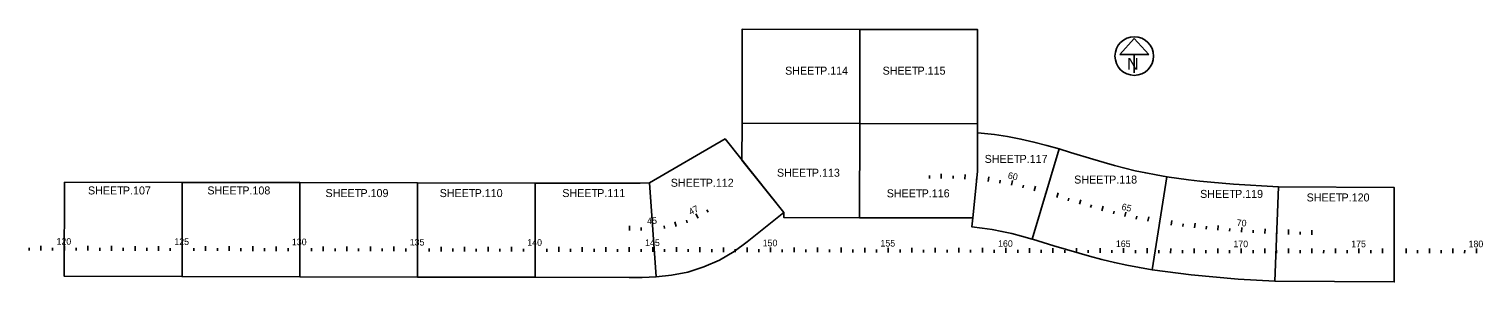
# Model space of a CAD drawing. Extents: x 129683 to 135859, y 574888 to 575962.
import ezdxf

# ---------------------------------------------------------------- set-up
doc = ezdxf.new("R2010")
doc.units = 0
for name, color, linetype in [('GE_P_Alignment_100_Stations', 7, 'Continuous'), ('SH_Masking', 7, 'Continuous'), ('SH_Named_Boundary', 7, 'Continuous'), ('SH_Text', 7, 'Continuous')]:
    doc.layers.add(name, color=color, linetype=linetype)

msp = doc.modelspace()

# ---------------------------------------------------------------- linework, layer by layer
at = {"layer": 'GE_P_Alignment_100_Stations'}
for p, q in [((133558.3, 575328), (133558.3, 575348)), ((133658.2, 575325.2), (133659.4, 575345.2)), ((133508.3, 575328.1), (133508.3, 575340.1)), ((133608.2, 575327.4), (133608.6, 575339.4)), ((133708, 575321.2), (133709.2, 575333.2)), ((133757.7, 575315.5), (133760.3, 575335.3)), ((133807.1, 575308.1), (133809.1, 575319.9)), ((133856.3, 575298.9), (133860.3, 575318.5)), ((133905.1, 575288), (133907.9, 575299.7)), ((133953.5, 575275.4), (133958.9, 575294.7)), ((134001.5, 575261.3), (134004.9, 575272.8)), ((134049.3, 575247), (134055.1, 575266.1)), ((134097.2, 575232.6), (134100.7, 575244.1)), ((134145.1, 575218.3), (134150.9, 575237.4)), ((132525.3, 575159.5), (132516.2, 575177.3)), ((132568.5, 575184.6), (132561.9, 575194.6)), ((134193, 575203.9), (134196.4, 575215.4)), ((134241.1, 575190.2), (134246.4, 575209.4)), ((134289.5, 575177.5), (134292.4, 575189.1)), ((134338.1, 575165.8), (134342.5, 575185.3)), ((134387, 575155.3), (134389.4, 575167)), ((134436, 575145.8), (134439.6, 575165.4)), ((132233.2, 575107.1), (132233.2, 575127.1)), ((132283.2, 575107.4), (132282.9, 575119.4)), ((132333.1, 575109.5), (132331.7, 575129.4)), ((132382.8, 575114.7), (132381.1, 575126.6)), ((132431.9, 575124.4), (132426.9, 575143.7)), ((132479.5, 575139.3), (132475.3, 575150.6)), ((134485.3, 575137.3), (134487.2, 575149.2)), ((134534.8, 575130), (134537.5, 575149.8)), ((134584.4, 575123.6), (134585.8, 575135.5)), ((134634, 575117.8), (134636.3, 575137.7)), ((134683.8, 575112.5), (134685, 575124.5)), ((134733.5, 575107.8), (134735.3, 575127.7)), ((134783.4, 575103.5), (134784.3, 575115.5)), ((134833.2, 575099.9), (134834.6, 575119.8)), ((134883.1, 575096.7), (134883.8, 575108.7)), ((134933, 575094.1), (134934, 575114)), ((134983, 575091.9), (134983.4, 575103.9)), ((135033, 575090.4), (135033.5, 575110.4)), ((135083, 575089.3), (135083.2, 575101.3)), ((135133, 575088.8), (135133.1, 575108.8)), ((129733, 575021.7), (129733, 575041.7)), ((129833, 575021.4), (129833, 575041.4)), ((129933, 575021.2), (129933, 575041.2)), ((130033, 575021), (130033, 575041)), ((130133, 575020.8), (130133, 575040.8)), ((130233, 575020.5), (130233, 575040.5)), ((130333, 575020.3), (130333, 575040.3)), ((130433, 575020.1), (130433, 575040.1)), ((130533, 575019.9), (130533, 575039.9)), ((130633, 575019.6), (130633, 575039.6)), ((130733, 575019.4), (130733, 575039.4)), ((130833, 575019.2), (130833, 575039.2)), ((130933, 575019), (130933, 575039)), ((131033, 575018.7), (131033, 575038.7)), ((131133, 575018.5), (131133, 575038.5)), ((131233, 575018.3), (131233, 575038.3)), ((131433, 575017.8), (131433, 575037.8)), ((131533, 575017.6), (131533, 575037.6)), ((131633, 575017.4), (131633, 575037.4)), ((131733, 575017.2), (131733, 575037.2)), ((131833, 575016.9), (131833, 575036.9)), ((131933, 575016.7), (131933, 575036.7)), ((132033, 575016.5), (132033, 575036.5)), ((132133, 575016.3), (132133, 575036.3)), ((132233, 575016), (132233, 575036)), ((132333, 575015.8), (132333, 575035.8)), ((132433, 575015.6), (132433, 575035.6)), ((132533, 575015.4), (132533, 575035.4)), ((129683, 575021.8), (129683, 575033.8)), ((129783, 575021.5), (129783, 575033.5)), ((129883, 575021.3), (129883, 575033.3)), ((129983, 575021.1), (129983, 575033.1)), ((130083, 575020.9), (130083, 575032.9)), ((130183, 575020.6), (130183, 575032.6)), ((130283, 575020.4), (130283, 575032.4)), ((130383, 575020.2), (130383, 575032.2)), ((130483, 575020), (130483, 575032)), ((130583, 575019.7), (130583, 575031.7)), ((130683, 575019.5), (130683, 575031.5)), ((130783, 575019.3), (130783, 575031.3)), ((130883, 575019.1), (130883, 575031.1)), ((130983, 575018.9), (130983, 575030.9)), ((131083, 575018.6), (131083, 575030.6)), ((131183, 575018.4), (131183, 575030.4)), ((131283, 575018.2), (131283, 575030.2)), ((131383, 575018), (131383, 575030)), ((131483, 575017.7), (131483, 575029.7)), ((131583, 575017.5), (131583, 575029.5)), ((131683, 575017.3), (131683, 575029.3)), ((131783, 575017.1), (131783, 575029.1)), ((131883, 575016.8), (131883, 575028.8)), ((131983, 575016.6), (131983, 575028.6)), ((132083, 575016.4), (132083, 575028.4)), ((132183, 575016.2), (132183, 575028.2)), ((132283, 575015.9), (132283, 575027.9)), ((132283, 575015.9), (132283, 575027.9)), ((132283, 575015.9), (132283, 575027.9)), ((132383, 575015.7), (132383, 575027.7)), ((132483, 575015.5), (132483, 575027.5)), ((132583, 575015.3), (132583, 575027.3)), ((132633, 575015.2), (132633, 575035.2)), ((132683, 575015), (132683, 575027)), ((132733, 575014.9), (132733, 575034.9)), ((132783, 575014.8), (132783, 575026.8)), ((132833, 575014.7), (132833, 575034.7)), ((132883, 575014.6), (132883, 575026.6)), ((132933, 575014.5), (132933, 575034.5)), ((132983, 575014.4), (132983, 575026.4)), ((133033, 575014.3), (133033, 575034.3)), ((133083, 575014.1), (133083, 575026.1)), ((133133, 575014), (133133, 575034)), ((133183, 575013.9), (133183, 575025.9)), ((133233, 575013.8), (133233, 575033.8)), ((133283, 575013.7), (133283, 575025.7)), ((133333, 575013.6), (133333, 575033.6)), ((133383, 575013.5), (133383, 575025.5)), ((133433, 575013.4), (133433, 575033.4)), ((133483, 575013.2), (133483, 575025.2)), ((133533, 575013.1), (133533, 575033.1)), ((133583, 575013), (133583, 575025)), ((133633, 575012.9), (133633, 575032.9)), ((133683, 575012.8), (133683, 575024.8)), ((133733, 575012.7), (133733, 575032.7)), ((133783, 575012.6), (133783, 575024.6)), ((133833, 575012.5), (133833, 575032.5)), ((133883, 575012.4), (133883, 575024.4)), ((133933, 575012.2), (133933, 575032.2)), ((133983, 575012.1), (133983, 575024.1)), ((134033, 575012), (134033, 575032)), ((134083, 575011.9), (134083, 575023.9)), ((134133, 575011.8), (134133, 575031.8)), ((134183, 575011.7), (134183, 575023.7)), ((134233, 575011.6), (134233, 575031.6)), ((134283, 575011.5), (134283, 575023.5)), ((134333, 575011.3), (134333, 575031.3)), ((134382.9, 575011.2), (134383, 575023.2)), ((134432.9, 575011.1), (134433, 575031.1)), ((134482.9, 575011), (134483, 575023)), ((134532.9, 575010.9), (134533, 575030.9)), ((134582.9, 575010.8), (134583, 575022.8)), ((134632.9, 575010.8), (134633, 575030.8)), ((134682.9, 575010.8), (134683, 575022.8)), ((134732.9, 575010.8), (134733, 575030.8)), ((134782.9, 575010.8), (134783, 575022.8)), ((134832.9, 575010.8), (134833, 575030.8)), ((134882.9, 575010.8), (134883, 575022.8)), ((134932.9, 575010.8), (134933, 575030.8)), ((134982.9, 575010.8), (134983, 575022.8)), ((135032.9, 575010.8), (135033, 575030.8)), ((135082.9, 575010.8), (135083, 575022.8)), ((135132.9, 575010.8), (135133, 575030.8)), ((135182.9, 575010.8), (135183, 575022.8)), ((135232.9, 575010.7), (135233, 575030.7)), ((135282.9, 575010.7), (135283, 575022.7)), ((135332.9, 575010.7), (135333, 575030.7)), ((135382.9, 575010.7), (135383, 575022.7)), ((135432.9, 575010.7), (135433, 575030.7)), ((135532.9, 575010.7), (135533, 575030.7)), ((135581.9, 575010.7), (135582, 575022.7)), ((135631.9, 575010.7), (135632, 575030.7)), ((135681.9, 575010.7), (135682, 575022.7)), ((135731.9, 575010.7), (135732, 575030.7)), ((135781.9, 575010.7), (135782, 575022.7)), ((135831.9, 575010.7), (135832, 575030.7))]:
    msp.add_line(p, q, dxfattribs=at)
at = {"layer": 'SH_Masking'}
msp.add_circle((134378.2, 575847.5), 82, dxfattribs=at)
at = {"layer": 'SH_Named_Boundary'}
for points in [[(132712.1, 575562.1), (132712.9, 575962.1), (133212.9, 575961), (133212, 575561)], [(133212.9, 575961), (133712.9, 575959.8), (133712, 575559.8), (133212, 575561)], [(132712.1, 575562.1), (132711.7, 575405.5), (132889.8, 575183.3), (132889.5, 575161.7), (133211.2, 575161), (133212, 575561)], [(133211.2, 575161), (133692.3, 575159.9), (133711.6, 575357.8), (133712, 575559.8), (133212, 575561)], [(132319.4, 575309), (132639.6, 575495.4), (132889.8, 575183.3), (132733.7, 575058.2), (132678.4, 575017.6), (132616, 574981.3), (132549.9, 574952.1), (132481, 574930.5), (132411.7, 574916.8), (132346.8, 574909.9)], [(133712, 575521.5), (133711.6, 575357.8), (133692.3, 575159.9), (133688.6, 575122.2), (133731.4, 575117.3), (133773.9, 575110.8), (133816.2, 575103), (133858.2, 575093.6), (133899.8, 575082.8), (133944, 575069.8), (134058.9, 575452.9), (134007.2, 575468.1), (133952, 575482.4), (133896.4, 575494.8), (133840.4, 575505.3), (133784, 575513.8), (133727.4, 575520.3)], [(134058.9, 575452.9), (134106.8, 575438.6), (134202.6, 575409.8), (134202.6, 575409.8), (134250.1, 575395.6), (134294, 575383), (134338.1, 575371.5), (134338.1, 575371.5), (134382.5, 575360.8), (134427.1, 575351.2), (134471.9, 575342.5), (134516.9, 575334.8), (134453.8, 574939.8), (134400.2, 574949), (134346.8, 574959.3), (134293.7, 574970.8), (134240.8, 574983.5), (134188.2, 574997.3), (134143.8, 575010), (134035.9, 575042.2), (133945.3, 575069.4), (133944, 575069.8)], [(129833.6, 575312.4), (130333.6, 575311.3), (130332.7, 574911.3), (129832.7, 574912.4)], [(130333.6, 575311.3), (130833.6, 575310.2), (130832.7, 574910.2), (130332.7, 574911.3)], [(130833.6, 575310.2), (131333.6, 575309.1), (131332.7, 574909.1), (130832.7, 574910.2)], [(131333.6, 575309.1), (131833.6, 575307.9), (131832.7, 574907.9), (131332.7, 574909.1)], [(131333.6, 575309.1), (131833.6, 575307.9), (131832.7, 574907.9), (131332.7, 574909.1)], [(131833.6, 575307.9), (132279.2, 575307.4), (132319.4, 575309), (132346.8, 574909.9), (132287.1, 574907.4), (132232.9, 574907.1), (131832.7, 574907.9)], [(134516.9, 575334.8), (134608.7, 575322.1), (134656.2, 575316.6), (134703.8, 575311.5), (134799.2, 575302.9), (134990.4, 575291.8), (134975.6, 574892.1), (134819.5, 574900.3), (134620.3, 574918.1), (134453.8, 574939.8)], [(134990.4, 575291.8), (135483, 575288.7), (135482.9, 574888.4), (134975.6, 574892.1)]]:
    msp.add_lwpolyline(points, close=True, dxfattribs=at)
at = {"layer": 'SH_Text'}
for p, q in [((134378.2, 575922.3), (134316.6, 575854)), ((134439.7, 575854), (134378.2, 575922.3)), ((134316.6, 575854), (134439.7, 575854)), ((134378.2, 575854), (134378.2, 575776.7))]:
    msp.add_line(p, q, dxfattribs=at)
msp.add_circle((134378.2, 575847.5), 82, dxfattribs=at)

# ---------------------------------------------------------------- texts
at = {"layer": 'GE_P_Alignment_100_Stations'}
for s, rotation, p in [('60', 348.43456, (133839.5, 575327.9)), ('65', 347.1729, (134322.3, 575195.1)), ('45', 3.91761, (132309.6, 575132.9)), ('47', 26.9864, (132493.4, 575171.3)), ('70', 356.06639, (134812.7, 575126.3)), ('120', 359.87155, (129799.5, 575046.5)), ('125', 359.87155, (130300, 575045.4)), ('130', 359.87155, (130799.5, 575044.3)), ('135', 359.87155, (131300, 575043.1)), ('140', 359.87155, (131799.5, 575042)), ('145', 359.87155, (132300, 575040.9)), ('150', 359.87155, (132799.5, 575039.8)), ('155', 359.87155, (133300, 575038.7)), ('160', 359.87155, (133799.5, 575037.5)), ('165', 359.87155, (134300, 575036.4)), ('170', 359.99184, (134799.5, 575035.8)), ('175', 359.99184, (135299.9, 575035.7)), ('180', 359.99184, (135798.5, 575035.7))]:
    msp.add_text(s, height=28, rotation=rotation, dxfattribs=at).set_placement(p)
at = {"layer": 'SH_Named_Boundary'}
for s, p in [('SHEET ', (132895, 575768.5)), ('P.114', (133043.5, 575768.5)), ('SHEET ', (133309.1, 575768.5)), ('P.115', (133457.5, 575768.5)), ('SHEET ', (133742.7, 575393.8)), ('P.117', (133891.2, 575393.8)), ('SHEET ', (132860.3, 575335.1)), ('P.113', (133008.8, 575335.1)), ('SHEET ', (129933.2, 575259.9)), ('P.107', (130081.7, 575259.9)), ('SHEET ', (130440.5, 575259.9)), ('P.108', (130589, 575259.9)), ('SHEET ', (130942.4, 575248.7)), ('P.109', (131090.9, 575248.7)), ('SHEET ', (131427.5, 575248.7)), ('P.110', (131576, 575248.7)), ('SHEET ', (131948.3, 575248.7)), ('P.111', (132096.8, 575248.7)), ('SHEET ', (132409.1, 575292.5)), ('P.112', (132557.6, 575292.5)), ('SHEET ', (134123, 575306.1)), ('P.118', (134271.5, 575306.1)), ('SHEET ', (133326.7, 575247.7)), ('P.116', (133475.1, 575247.7)), ('SHEET ', (134658.1, 575245.2)), ('P.119', (134806.5, 575245.2)), ('SHEET ', (135110.5, 575230.1)), ('P.120', (135259, 575230.1))]:
    msp.add_text(s, height=34, dxfattribs=at).set_placement(p)
at = {"layer": 'SH_Text'}
msp.add_text('N', height=50, dxfattribs=at).set_placement((134347.9, 575789.3))

doc.saveas('drawing.dxf')
